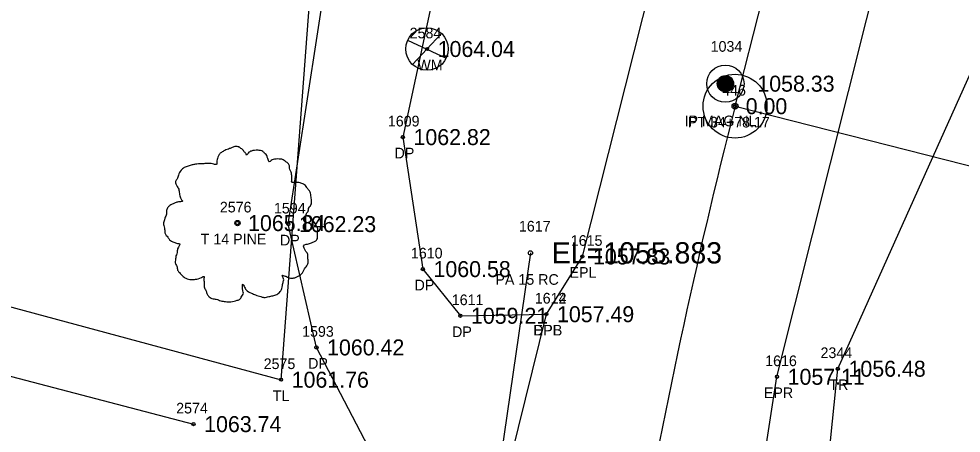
# Model space of a CAD drawing. Extents: x 1578957 to 1581675, y 1115963 to 1120391.
# Drawn here: x 1580461 to 1580549.5, y 1118649.2 to 1118688.1 of the extents above; entities that cross this region are included whole.
import ezdxf

# ---------------------------------------------------------------- set-up
doc = ezdxf.new("R2010")
doc.units = 0
for name, color, linetype in [('RD_EX_DR_Pipe', 7, 'Continuous'), ('RD_EX_DR_Pipe_txCode', 7, 'Continuous'), ('RD_EX_Driveway', 7, 'Continuous'), ('RD_EX_Driveway_txCode', 7, 'Continuous'), ('RD_EX_DV_Prop_txCode', 7, 'Continuous'), ('RD_EX_DV_PropPin', 7, 'Continuous'), ('RD_EX_Road', 7, 'Continuous'), ('RD_EX_Road_txCode', 7, 'Continuous'), ('RD_EX_TX_Driveway_ELEV', 7, 'Continuous'), ('RD_EX_TX_DV_Prop_ELEV', 7, 'Continuous'), ('RD_EX_TX_Road_ELEV', 7, 'Continuous'), ('RD_EX_TX_UT_ELEV', 7, 'Continuous'), ('RD_EX_TX_VEG_ELEV', 7, 'Continuous'), ('RD_EX_UT', 7, 'Continuous'), ('RD_EX_UT_txCode', 7, 'Continuous'), ('RD_EX_VEG', 7, 'Continuous'), ('RD_EX_VEG_txCode', 7, 'Continuous'), ('RD_HC_Cl', 7, 'Continuous'), ('RD_HC_Data', 7, 'Continuous'), ('RD_HC_Survey_ELEV', 7, 'Continuous'), ('RD_HC_txCode', 7, 'Continuous'), ('RD_SMD_Locator', 7, 'Continuous'), ('RD_TX_Pipe_ElevEX', 7, 'Continuous')]:
    doc.layers.add(name, color=color, linetype=linetype)

msp = doc.modelspace()

# ---------------------------------------------------------------- linework, layer by layer
at = {"layer": 'RD_EX_DR_Pipe'}
msp.add_line((1580509.048, 1118666.096), (1580500.321, 1118605.868), dxfattribs=at)
at = {"layer": 'RD_EX_Driveway'}
for points in [[(1580430.858, 1118772.823), (1580473.345, 1118775.338), (1580493.575, 1118772.785), (1580504.69, 1118768.055), (1580513.169, 1118758.027), (1580513.455, 1118741.379), (1580500.525, 1118693.186), (1580497.064, 1118676.968), (1580498.942, 1118664.57), (1580502.461, 1118660.184), (1580510.539, 1118660.334)], [(1580503.124, 1118611.134), (1580499.883, 1118612.99), (1580494.922, 1118612.852), (1580490.544, 1118611.044), (1580492.21, 1118614.127), (1580481.594, 1118620.673), (1580491.665, 1118637.485), (1580495.355, 1118644.978), (1580488.949, 1118657.214), (1580486.307, 1118668.792), (1580489.931, 1118692.365), (1580499.055, 1118734.88), (1580498.977, 1118746.365), (1580495.647, 1118753.462), (1580485.289, 1118760.72), (1580470.799, 1118764.239), (1580428.28, 1118761.959)]]:
    msp.add_lwpolyline(points, dxfattribs=at)
at = {"layer": 'RD_EX_DV_PropPin'}
for p, q in [((1580526.72, 1118681.559), (1580526.72, 1118682.412)), ((1580526.755, 1118681.511), (1580526.755, 1118682.459)), ((1580526.79, 1118681.47), (1580526.79, 1118682.5)), ((1580526.825, 1118681.434), (1580526.825, 1118682.536)), ((1580526.86, 1118681.403), (1580526.86, 1118682.567)), ((1580526.895, 1118681.375), (1580526.895, 1118682.595)), ((1580526.93, 1118681.351), (1580526.93, 1118682.62)), ((1580526.965, 1118681.329), (1580526.965, 1118682.642)), ((1580527, 1118681.31), (1580527, 1118682.661)), ((1580527.035, 1118681.292), (1580527.035, 1118682.678)), ((1580527.07, 1118681.278), (1580527.07, 1118682.693)), ((1580527.105, 1118681.265), (1580527.105, 1118682.706)), ((1580527.14, 1118681.254), (1580527.14, 1118682.717)), ((1580527.175, 1118681.245), (1580527.175, 1118682.726)), ((1580527.21, 1118681.237), (1580527.21, 1118682.733)), ((1580527.245, 1118681.231), (1580527.245, 1118682.739)), ((1580527.28, 1118681.227), (1580527.28, 1118682.743)), ((1580527.315, 1118681.225), (1580527.315, 1118682.745)), ((1580527.35, 1118681.224), (1580527.35, 1118682.746)), ((1580527.385, 1118681.225), (1580527.385, 1118682.745)), ((1580527.42, 1118681.227), (1580527.42, 1118682.743)), ((1580527.455, 1118681.231), (1580527.455, 1118682.739)), ((1580527.49, 1118681.237), (1580527.49, 1118682.733)), ((1580527.525, 1118681.245), (1580527.525, 1118682.726)), ((1580527.56, 1118681.254), (1580527.56, 1118682.717)), ((1580527.595, 1118681.265), (1580527.595, 1118682.706)), ((1580527.63, 1118681.278), (1580527.63, 1118682.693)), ((1580527.665, 1118681.292), (1580527.665, 1118682.678)), ((1580527.7, 1118681.31), (1580527.7, 1118682.661)), ((1580527.735, 1118681.329), (1580527.735, 1118682.642)), ((1580527.77, 1118681.351), (1580527.77, 1118682.62)), ((1580527.805, 1118681.375), (1580527.805, 1118682.595)), ((1580527.84, 1118681.403), (1580527.84, 1118682.567)), ((1580527.875, 1118681.434), (1580527.875, 1118682.536)), ((1580527.91, 1118681.47), (1580527.91, 1118682.5)), ((1580527.945, 1118681.511), (1580527.945, 1118682.459)), ((1580527.98, 1118681.559), (1580527.98, 1118682.412)), ((1580526.615, 1118681.789), (1580526.615, 1118682.181)), ((1580526.65, 1118681.687), (1580526.65, 1118682.283)), ((1580526.685, 1118681.616), (1580526.685, 1118682.355)), ((1580528.015, 1118681.616), (1580528.015, 1118682.355)), ((1580528.05, 1118681.687), (1580528.05, 1118682.283)), ((1580528.085, 1118681.789), (1580528.085, 1118682.181))]:
    msp.add_line(p, q, dxfattribs=at)
for radius in [1.75, 0.761]:
    msp.add_circle((1580527.35, 1118681.985), radius, dxfattribs=at)
at = {"layer": 'RD_EX_Road'}
for points in [[(1580473.875, 1118362.545), (1580483.476, 1118411.51), (1580489.891, 1118460.733), (1580494.851, 1118510.571), (1580499.158, 1118559.986), (1580504.007, 1118606.077), (1580503.124, 1118611.134), (1580505.284, 1118639.056), (1580510.539, 1118660.334), (1580513.919, 1118665.755), (1580524.452, 1118707.451), (1580537.087, 1118755.411), (1580548.08, 1118804.242), (1580553.771, 1118847.319), (1580551.542, 1118852.657), (1580554.273, 1118873), (1580557.664, 1118878.489), (1580561.509, 1118902.856), (1580569.284, 1118952.033)], [(1580493.79, 1118358.466), (1580503.62, 1118407.198), (1580510.352, 1118458.033), (1580515.162, 1118508.07), (1580519.106, 1118556.963), (1580525.123, 1118608.819), (1580532.195, 1118654.454), (1580543.96, 1118701.357), (1580546.317, 1118710.018), (1580556.92, 1118750.178), (1580559.572, 1118760.221), (1580560.059, 1118761.897), (1580568.211, 1118801.71), (1580574.887, 1118850.465), (1580581.375, 1118900.878), (1580589.102, 1118945.81)]]:
    msp.add_lwpolyline(points, dxfattribs=at)
at = {"layer": 'RD_EX_UT'}
for p, q in [((1580497.498, 1118686.08), (1580501.128, 1118684.367)), ((1580497.979, 1118683.784), (1580500.646, 1118686.681))]:
    msp.add_line(p, q, dxfattribs=at)
msp.add_circle((1580499.331, 1118685.243), 2, dxfattribs=at)
at = {"layer": 'RD_EX_VEG'}
msp.add_line((1580417.704, 1118665.668), (1580477.408, 1118650.009), dxfattribs=at)
for points in [[(1580421.913, 1118671.359), (1580485.624, 1118654.178), (1580489.679, 1118707.906), (1580496.866, 1118741.571), (1580494.203, 1118750.409), (1580484.589, 1118756.1), (1580440.403, 1118760.402)], [(1580593.07, 1118446.845), (1580515.915, 1118445.773), (1580522.895, 1118507.713), (1580537.911, 1118655.21), (1580556.145, 1118695.918), (1580596.371, 1118717.961), (1580655.86, 1118691.542)]]:
    msp.add_lwpolyline(points, dxfattribs=at)
for centre, radius in [((1580481.533, 1118668.892), 0.25), ((1580481.52, 1118668.873), 0.0001)]:
    msp.add_circle(centre, radius, dxfattribs=at)
for points in [[(1580481.665, 1118676.059), (1580481.365, 1118676.084), (1580481.04, 1118675.984), (1580480.79, 1118675.884), (1580480.565, 1118675.809), (1580480.34, 1118675.709), (1580480.04, 1118675.535), (1580479.815, 1118675.335), (1580479.69, 1118675.085), (1580479.64, 1118674.86), (1580479.591, 1118674.585), (1580479.591, 1118674.41), (1580479.466, 1118674.385), (1580479.316, 1118674.41), (1580479.066, 1118674.485), (1580478.816, 1118674.485), (1580478.566, 1118674.485), (1580478.216, 1118674.46), (1580477.866, 1118674.46), (1580477.591, 1118674.41), (1580477.267, 1118674.36), (1580476.892, 1118674.235), (1580476.542, 1118674.11), (1580476.242, 1118673.86), (1580475.992, 1118673.386), (1580475.867, 1118673.036), (1580475.717, 1118672.786), (1580475.867, 1118672.336), (1580476.042, 1118671.986), (1580476.067, 1118671.786), (1580476.142, 1118671.361), (1580476.242, 1118671.137), (1580476.367, 1118670.937), (1580476.292, 1118670.912), (1580475.917, 1118670.862), (1580475.617, 1118670.762), (1580475.192, 1118670.537), (1580474.968, 1118670.312), (1580474.868, 1118669.987), (1580474.843, 1118669.637), (1580474.743, 1118669.437), (1580474.668, 1118669.162), (1580474.643, 1118669.087), (1580474.593, 1118668.763), (1580474.693, 1118668.313), (1580474.718, 1118667.963), (1580474.843, 1118667.738), (1580474.993, 1118667.563), (1580475.167, 1118667.313), (1580475.567, 1118667.088), (1580475.892, 1118666.988), (1580476.092, 1118666.963), (1580475.917, 1118666.464), (1580475.867, 1118666.114), (1580475.742, 1118665.714), (1580475.742, 1118665.639), (1580475.692, 1118665.164), (1580475.842, 1118664.839), (1580475.917, 1118664.464), (1580476.092, 1118664.24), (1580476.367, 1118663.94), (1580476.692, 1118663.715), (1580477.192, 1118663.59), (1580477.591, 1118663.615), (1580478.166, 1118663.79), (1580478.416, 1118663.865), (1580478.391, 1118663.69), (1580478.416, 1118663.315), (1580478.416, 1118662.89), (1580478.566, 1118662.565), (1580478.666, 1118662.29), (1580478.816, 1118662.04), (1580479.141, 1118661.816), (1580479.541, 1118661.741), (1580479.965, 1118661.591), (1580480.415, 1118661.516), (1580480.915, 1118661.491), (1580481.515, 1118661.641), (1580481.79, 1118661.766), (1580481.89, 1118661.941), (1580482.089, 1118662.315), (1580482.039, 1118662.54), (1580482.064, 1118663.14), (1580482.164, 1118662.965), (1580482.339, 1118662.615), (1580482.839, 1118662.315), (1580483.239, 1118662.14), (1580483.714, 1118661.99), (1580484.014, 1118661.916), (1580484.488, 1118661.99), (1580484.863, 1118662.065), (1580485.238, 1118662.19), (1580485.538, 1118662.465), (1580485.713, 1118662.74), (1580485.763, 1118663.015), (1580485.838, 1118663.39), (1580485.888, 1118663.565)], [(1580485.888, 1118663.565), (1580485.813, 1118663.74), (1580485.763, 1118663.99), (1580485.838, 1118663.965), (1580486.013, 1118663.915), (1580486.288, 1118663.79), (1580486.513, 1118663.715), (1580486.837, 1118663.74), (1580487.112, 1118663.84), (1580487.562, 1118664.115), (1580487.837, 1118664.589), (1580488.112, 1118664.989), (1580488.187, 1118665.314), (1580488.137, 1118665.539), (1580488.112, 1118666.039), (1580487.912, 1118666.289), (1580487.862, 1118666.414), (1580487.762, 1118666.813), (1580487.837, 1118666.863), (1580488.112, 1118666.913), (1580488.487, 1118667.038), (1580488.762, 1118667.163), (1580488.986, 1118667.338), (1580489.061, 1118667.563), (1580489.036, 1118667.963), (1580489.086, 1118668.363), (1580489.011, 1118668.513), (1580488.911, 1118668.663), (1580488.836, 1118668.863), (1580488.687, 1118669.012), (1580488.587, 1118669.162), (1580488.487, 1118669.262), (1580488.362, 1118669.412), (1580488.187, 1118669.537), (1580488.037, 1118669.587), (1580487.987, 1118669.737), (1580488.137, 1118669.937), (1580488.187, 1118670.037), (1580488.212, 1118670.262), (1580488.437, 1118670.612), (1580488.487, 1118671.012), (1580488.437, 1118671.436), (1580488.387, 1118671.711), (1580488.237, 1118671.986), (1580488.037, 1118672.236), (1580487.912, 1118672.411), (1580487.737, 1118672.536), (1580487.412, 1118672.661), (1580487.162, 1118672.711), (1580486.812, 1118672.711), (1580486.612, 1118672.761), (1580486.637, 1118672.811), (1580486.637, 1118672.961), (1580486.637, 1118673.236), (1580486.562, 1118673.685), (1580486.413, 1118674.185), (1580486.413, 1118674.21), (1580486.313, 1118674.46), (1580486.088, 1118674.66), (1580485.913, 1118674.76), (1580485.713, 1118674.885), (1580485.463, 1118674.91), (1580485.163, 1118674.91), (1580484.888, 1118674.86), (1580484.688, 1118674.76), (1580484.513, 1118674.635), (1580484.438, 1118674.785), (1580484.338, 1118675.085), (1580484.288, 1118675.235), (1580484.139, 1118675.41), (1580483.914, 1118675.61), (1580483.464, 1118675.734), (1580482.839, 1118675.66), (1580482.539, 1118675.46), (1580482.389, 1118675.285), (1580482.339, 1118675.41), (1580482.139, 1118675.61), (1580482.039, 1118675.784), (1580481.865, 1118675.909), (1580481.715, 1118676.009), (1580481.615, 1118676.059)]]:
    msp.add_spline(points, degree=3, dxfattribs=at)
at = {"layer": 'RD_HC_Cl'}
msp.add_line((1580528.255, 1118679.871), (1580548.048, 1118757.839), dxfattribs=at)
msp.add_arc((1581096.907, 1118535.516), 586.689, 165.756019, 174.528137, dxfattribs=at)
at = {"layer": 'RD_HC_Data'}
msp.add_line((1580528.255, 1118679.871), (1580640.648, 1118651.34), dxfattribs=at)
for centre, radius in [((1580528.255, 1118679.872), 3), ((1580528.255, 1118679.871), 0.282)]:
    msp.add_circle(centre, radius, dxfattribs=at)
at = {"layer": 'RD_SMD_Locator'}
for centre, radius in [((1580499.331, 1118685.243), 0.15), ((1580527.35, 1118681.985), 0.15), ((1580528.255, 1118679.871), 0.15), ((1580497.064, 1118676.968), 0.15), ((1580481.533, 1118668.892), 0.15), ((1580486.307, 1118668.792), 0.15), ((1580509.048, 1118666.096), 0.2), ((1580513.919, 1118665.755), 0.15), ((1580498.942, 1118664.57), 0.15), ((1580502.461, 1118660.184), 0.15), ((1580510.539, 1118660.334), 0.15), ((1580510.539, 1118660.334), 0.15), ((1580488.949, 1118657.214), 0.15), ((1580537.911, 1118655.21), 0.15), ((1580485.624, 1118654.178), 0.15), ((1580532.195, 1118654.454), 0.15), ((1580477.408, 1118650.009), 0.15)]:
    msp.add_circle(centre, radius, dxfattribs=at)

# ---------------------------------------------------------------- texts
at = {"layer": 'RD_EX_DR_Pipe_txCode'}
for s, p in [('1617', (1580507.962, 1118668.096)), ('PA 15 RC', (1580505.757, 1118663.096))]:
    msp.add_text(s, height=1, dxfattribs=at).set_placement(p)
at = {"layer": 'RD_EX_Driveway_txCode'}
for s, p in [('1609', (1580495.654, 1118677.968)), ('DP', (1580496.284, 1118674.968)), ('1594', (1580484.96, 1118669.792)), ('DP', (1580485.527, 1118666.792)), ('1610', (1580497.816, 1118665.57)), ('DP', (1580498.162, 1118662.57)), ('1611', (1580501.658, 1118661.184)), ('1612', (1580509.453, 1118661.334)), ('1593', (1580487.602, 1118658.214)), ('DP', (1580501.681, 1118658.184)), ('DPB', (1580509.287, 1118658.334)), ('DP', (1580488.169, 1118655.214))]:
    msp.add_text(s, height=1, dxfattribs=at).set_placement(p)
at = {"layer": 'RD_EX_DV_Prop_txCode'}
for s, p in [('1034', (1580525.964, 1118684.985)), ('IP MAG NL', (1580523.516, 1118677.985))]:
    msp.add_text(s, height=1, dxfattribs=at).set_placement(p)
at = {"layer": 'RD_EX_Road_txCode'}
for s, p in [('1615', (1580512.832, 1118666.755)), ('EPL', (1580512.714, 1118663.755)), ('1614', (1580509.453, 1118661.334)), ('EPL', (1580509.335, 1118658.334)), ('1616', (1580531.084, 1118655.454)), ('EPR', (1580530.966, 1118652.454))]:
    msp.add_text(s, height=1, dxfattribs=at).set_placement(p)
at = {"layer": 'RD_EX_TX_Driveway_ELEV'}
for s, p in [('1062.82', (1580498.064, 1118676.218)), ('1062.23', (1580487.307, 1118668.042)), ('1060.58', (1580499.942, 1118663.82)), ('1059.21', (1580503.461, 1118659.434)), ('1057.49', (1580511.539, 1118659.584)), ('1060.42', (1580489.949, 1118656.464))]:
    msp.add_text(s, height=1.5, dxfattribs=at).set_placement(p)
at = {"layer": 'RD_EX_TX_DV_Prop_ELEV'}
msp.add_text('1058.33', height=1.5, dxfattribs=at).set_placement((1580530.35, 1118681.235))
at = {"layer": 'RD_EX_TX_Road_ELEV'}
for s, p in [('1057.83', (1580514.919, 1118665.005)), ('1057.49', (1580511.539, 1118659.584)), ('1057.11', (1580533.195, 1118653.704))]:
    msp.add_text(s, height=1.5, dxfattribs=at).set_placement(p)
at = {"layer": 'RD_EX_TX_UT_ELEV'}
msp.add_text('1064.04', height=1.5, dxfattribs=at).set_placement((1580500.331, 1118684.493))
at = {"layer": 'RD_EX_TX_VEG_ELEV'}
for s, p in [('1065.84', (1580482.533, 1118668.142)), ('1056.48', (1580538.911, 1118654.46)), ('1061.76', (1580486.624, 1118653.428)), ('1063.74', (1580478.408, 1118649.259))]:
    msp.add_text(s, height=1.5, dxfattribs=at).set_placement(p)
at = {"layer": 'RD_EX_UT_txCode'}
for s, p in [('2584', (1580497.701, 1118686.243)), ('WM', (1580498.425, 1118683.243))]:
    msp.add_text(s, height=1, dxfattribs=at).set_placement(p)
at = {"layer": 'RD_EX_VEG_txCode'}
for s, p in [('2576', (1580479.879, 1118669.892)), ('T 14 PINE', (1580478.08, 1118666.892)), ('2344', (1580536.281, 1118656.21)), ('2575', (1580483.994, 1118655.178)), ('TR', (1580537.115, 1118653.21)), ('TL', (1580484.852, 1118652.178)), ('2574', (1580475.778, 1118651.009))]:
    msp.add_text(s, height=1, dxfattribs=at).set_placement(p)
at = {"layer": 'RD_HC_Survey_ELEV'}
msp.add_text('0.00', height=1.5, dxfattribs=at).set_placement((1580529.255, 1118679.121))
at = {"layer": 'RD_HC_txCode'}
for s, p in [('446', (1580527.05, 1118680.871)), ('PT 34+78.17', (1580523.83, 1118677.871))]:
    msp.add_text(s, height=1, dxfattribs=at).set_placement(p)
at = {"layer": 'RD_TX_Pipe_ElevEX'}
msp.add_text('EL=1055.883', height=2, dxfattribs=at).set_placement((1580511.048, 1118665.096))

doc.saveas('drawing.dxf')
